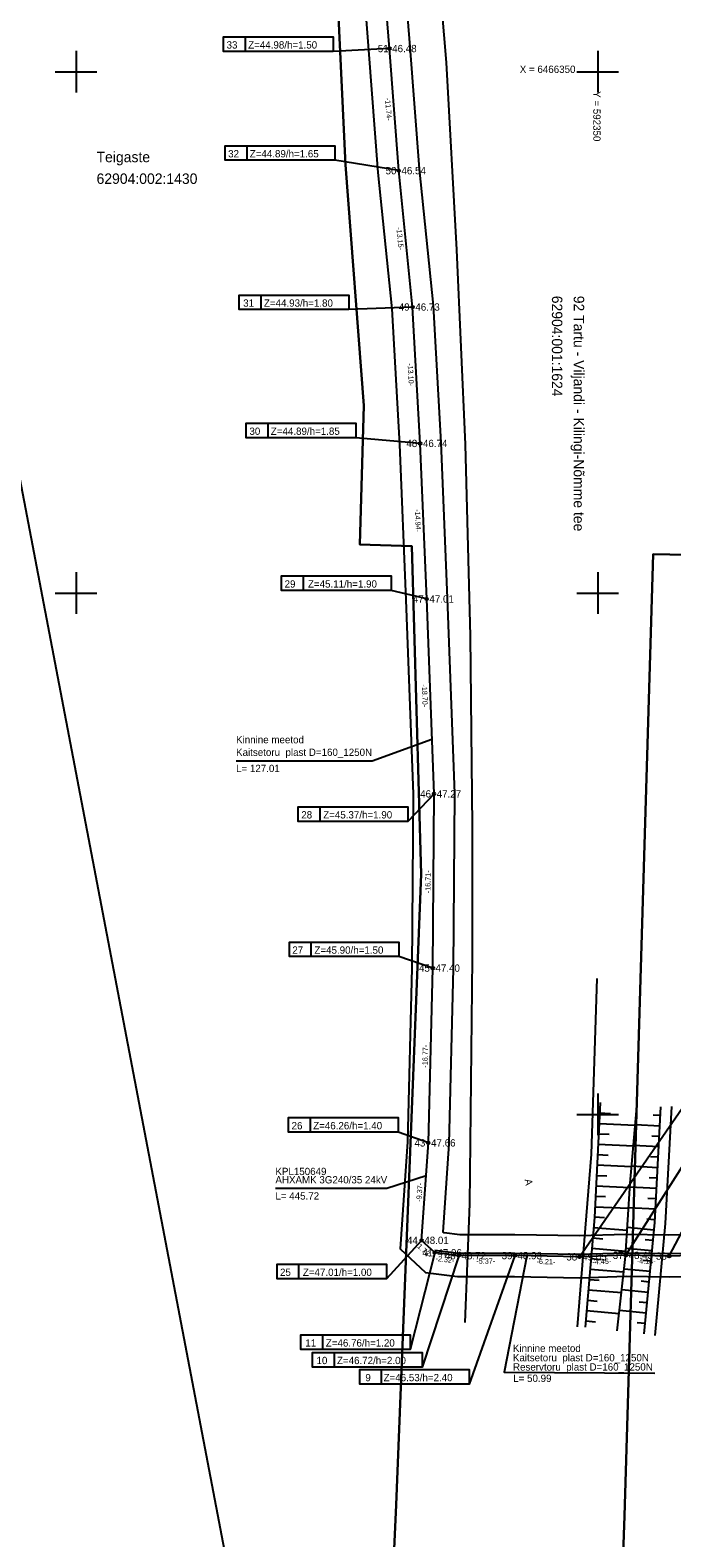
# Model space of a CAD drawing. Extents: x 592082 to 595437, y 6463338 to 6467739.
# Drawn here: x 592295.6 to 592357.1, y 6466209.4 to 6466354 of the extents above; entities that cross this region are included whole.
import ezdxf

# ---------------------------------------------------------------- set-up
doc = ezdxf.new("R2010")
doc.units = 0
for name, color, linetype in [('ABIJOONIS', 7, 'Continuous'), ('JOONSIDE', 7, 'Continuous'), ('KOORDPUNKT', 7, 'Continuous'), ('KPKAABEL', 7, 'Continuous'), ('MOOTKORG-EH2000', 7, 'Continuous'), ('MOOTMPUNKT', 7, 'Continuous'), ('MOOTNR', 7, 'Continuous'), ('MOOTPIIR', 7, 'Continuous'), ('PIIR', 7, 'Continuous'), ('RELJEEF', 7, 'Continuous'), ('TEE', 7, 'Continuous'), ('VORK', 7, 'Continuous'), ('VORMISTUS', 7, 'Continuous')]:
    doc.layers.add(name, color=color, linetype=linetype)

msp = doc.modelspace()

# ---------------------------------------------------------------- linework, layer by layer
at = {"layer": 'ABIJOONIS'}
for points in [[(592330.04, 6466352.22), (592324.63, 6466351.94), (592314.13, 6466351.94), (592314.13, 6466353.34), (592324.63, 6466353.34), (592324.63, 6466351.94)], [(592316.23, 6466351.94), (592316.23, 6466353.34)], [(592330.93, 6466340.51), (592324.8, 6466341.5), (592314.3, 6466341.5), (592314.3, 6466342.9), (592324.8, 6466342.9), (592324.8, 6466341.5)], [(592316.4, 6466341.5), (592316.4, 6466342.9)], [(592332.26, 6466327.43), (592326.15, 6466327.18), (592315.65, 6466327.18), (592315.65, 6466328.58), (592326.15, 6466328.58), (592326.15, 6466327.18)], [(592317.75, 6466327.18), (592317.75, 6466328.58)], [(592332.99, 6466314.35), (592326.82, 6466314.89), (592316.32, 6466314.89), (592316.32, 6466316.29), (592326.82, 6466316.29), (592326.82, 6466314.89)], [(592318.42, 6466314.89), (592318.42, 6466316.29)], [(592333.61, 6466299.43), (592330.19, 6466300.24), (592319.69, 6466300.24), (592319.69, 6466301.64), (592330.19, 6466301.64), (592330.19, 6466300.24)], [(592321.79, 6466300.24), (592321.79, 6466301.64)], [(592334.31, 6466280.74), (592331.79, 6466278.1), (592321.29, 6466278.1), (592321.29, 6466279.5), (592331.79, 6466279.5), (592331.79, 6466278.1)], [(592323.39, 6466278.1), (592323.39, 6466279.5)], [(592334.19, 6466264.03), (592330.95, 6466265.13), (592320.45, 6466265.13), (592320.45, 6466266.53), (592330.95, 6466266.53), (592330.95, 6466265.13)], [(592322.55, 6466265.13), (592322.55, 6466266.53)], [(592348.25, 6466236.34), (592362.1, 6466256.38), (592372.6, 6466256.38), (592372.6, 6466257.78), (592362.1, 6466257.78), (592362.1, 6466256.38)], [(592352.7, 6466236.49), (592364.21, 6466254.61), (592374.71, 6466254.61), (592374.71, 6466256.01), (592364.21, 6466256.01), (592364.21, 6466254.61)], [(592356.84, 6466236.41), (592365.39, 6466252.59), (592375.89, 6466252.59), (592375.89, 6466253.99), (592365.39, 6466253.99), (592365.39, 6466252.59)], [(592333.77, 6466247.27), (592330.87, 6466248.29), (592320.37, 6466248.29), (592320.37, 6466249.69), (592330.87, 6466249.69), (592330.87, 6466248.29)], [(592322.47, 6466248.29), (592322.47, 6466249.69)], [(592333.12, 6466237.92), (592329.77, 6466234.23), (592319.27, 6466234.23), (592319.27, 6466235.63), (592329.77, 6466235.63), (592329.77, 6466234.23)], [(592334.38, 6466236.74), (592332.04, 6466227.45), (592321.54, 6466227.45), (592321.54, 6466228.85), (592332.04, 6466228.85), (592332.04, 6466227.45)], [(592321.37, 6466234.23), (592321.37, 6466235.63)], [(592336.68, 6466236.45), (592333.18, 6466225.77), (592322.68, 6466225.77), (592322.68, 6466227.17), (592333.18, 6466227.17), (592333.18, 6466225.77)], [(592342.05, 6466236.46), (592337.69, 6466224.13), (592327.19, 6466224.13), (592327.19, 6466225.53), (592337.69, 6466225.53), (592337.69, 6466224.13)], [(592323.64, 6466227.45), (592323.64, 6466228.85)], [(592324.78, 6466225.77), (592324.78, 6466227.17)], [(592329.29, 6466224.13), (592329.29, 6466225.53)]]:
    msp.add_lwpolyline(points, dxfattribs=at)
at = {"layer": 'KOORDPUNKT'}
for centre, radius in [((592330.04, 6466352.22), 0.125), ((592330.04, 6466352.22), 0.011), ((592330.04, 6466352.22), 0.0125), ((592330.04, 6466352.22), 0.00511), ((592330.04, 6466352.22), 0.00659), ((592330.04, 6466352.22), 0.00807), ((592330.04, 6466352.22), 0.00955), ((592330.04, 6466352.22), 0.00215), ((592330.04, 6466352.22), 0.00363), ((592330.93, 6466340.51), 0.125), ((592330.93, 6466340.51), 0.00511), ((592330.93, 6466340.51), 0.00659), ((592330.93, 6466340.51), 0.00807), ((592330.93, 6466340.51), 0.00955), ((592330.93, 6466340.51), 0.011), ((592330.93, 6466340.51), 0.0125), ((592330.93, 6466340.51), 0.00215), ((592330.93, 6466340.51), 0.00363), ((592332.26, 6466327.43), 0.125), ((592332.26, 6466327.43), 0.011), ((592332.26, 6466327.43), 0.0125), ((592332.26, 6466327.43), 0.00511), ((592332.26, 6466327.43), 0.00659), ((592332.26, 6466327.43), 0.00807), ((592332.26, 6466327.43), 0.00955), ((592332.26, 6466327.43), 0.00215), ((592332.26, 6466327.43), 0.00363), ((592332.99, 6466314.35), 0.125), ((592332.99, 6466314.35), 0.011), ((592332.99, 6466314.35), 0.0125), ((592332.99, 6466314.35), 0.00659), ((592332.99, 6466314.35), 0.00807), ((592332.99, 6466314.35), 0.00955), ((592332.99, 6466314.35), 0.00215), ((592332.99, 6466314.35), 0.00363), ((592332.99, 6466314.35), 0.00511), ((592333.61, 6466299.43), 0.125), ((592333.61, 6466299.43), 0.00807), ((592333.61, 6466299.43), 0.00955), ((592333.61, 6466299.43), 0.011), ((592333.61, 6466299.43), 0.0125), ((592333.61, 6466299.43), 0.00511), ((592333.61, 6466299.43), 0.00659), ((592333.61, 6466299.43), 0.00215), ((592333.61, 6466299.43), 0.00363), ((592334.31, 6466280.74), 0.125), ((592334.31, 6466280.74), 0.011), ((592334.31, 6466280.74), 0.0125), ((592334.31, 6466280.74), 0.00511), ((592334.31, 6466280.74), 0.00659), ((592334.31, 6466280.74), 0.00807), ((592334.31, 6466280.74), 0.00955), ((592334.31, 6466280.74), 0.00215), ((592334.31, 6466280.74), 0.00363), ((592334.19, 6466264.03), 0.125), ((592334.19, 6466264.03), 0.011), ((592334.19, 6466264.03), 0.0125), ((592334.19, 6466264.03), 0.00807), ((592334.19, 6466264.03), 0.00955), ((592334.19, 6466264.03), 0.00215), ((592334.19, 6466264.03), 0.00363), ((592334.19, 6466264.03), 0.00511), ((592334.19, 6466264.03), 0.00659), ((592333.77, 6466247.27), 0.125), ((592333.77, 6466247.27), 0.011), ((592333.77, 6466247.27), 0.0125), ((592333.77, 6466247.27), 0.00511), ((592333.77, 6466247.27), 0.00659), ((592333.77, 6466247.27), 0.00807), ((592333.77, 6466247.27), 0.00955), ((592333.77, 6466247.27), 0.00215), ((592333.77, 6466247.27), 0.00363), ((592333.12, 6466237.92), 0.125), ((592333.12, 6466237.92), 0.00955), ((592333.12, 6466237.92), 0.011), ((592333.12, 6466237.92), 0.0125), ((592333.12, 6466237.92), 0.00511), ((592333.12, 6466237.92), 0.00659), ((592333.12, 6466237.92), 0.00807), ((592333.12, 6466237.92), 0.00215), ((592333.12, 6466237.92), 0.00363), ((592334.38, 6466236.74), 0.125), ((592334.38, 6466236.74), 0.011), ((592334.38, 6466236.74), 0.0125), ((592334.38, 6466236.74), 0.00363), ((592334.38, 6466236.74), 0.00511), ((592334.38, 6466236.74), 0.00659), ((592334.38, 6466236.74), 0.00807), ((592334.38, 6466236.74), 0.00955), ((592334.38, 6466236.74), 0.00215), ((592336.68, 6466236.45), 0.125), ((592336.68, 6466236.45), 0.011), ((592336.68, 6466236.45), 0.0125), ((592336.68, 6466236.45), 0.00807), ((592336.68, 6466236.45), 0.00955), ((592336.68, 6466236.45), 0.00215), ((592336.68, 6466236.45), 0.00363), ((592336.68, 6466236.45), 0.00511), ((592336.68, 6466236.45), 0.00659), ((592342.05, 6466236.46), 0.125), ((592342.05, 6466236.46), 0.0125), ((592342.05, 6466236.46), 0.00215), ((592342.05, 6466236.46), 0.00363), ((592342.05, 6466236.46), 0.00511), ((592342.05, 6466236.46), 0.00659), ((592342.05, 6466236.46), 0.00807), ((592342.05, 6466236.46), 0.00955), ((592342.05, 6466236.46), 0.011), ((592348.25, 6466236.34), 0.125), ((592348.25, 6466236.34), 0.00807), ((592348.25, 6466236.34), 0.00955), ((592348.25, 6466236.34), 0.011), ((592348.25, 6466236.34), 0.0125), ((592348.25, 6466236.34), 0.00511), ((592348.25, 6466236.34), 0.00659), ((592348.25, 6466236.34), 0.00215), ((592348.25, 6466236.34), 0.00363), ((592352.7, 6466236.49), 0.125), ((592352.7, 6466236.49), 0.0125), ((592352.7, 6466236.49), 0.00511), ((592352.7, 6466236.49), 0.00659), ((592352.7, 6466236.49), 0.00807), ((592352.7, 6466236.49), 0.00955), ((592352.7, 6466236.49), 0.011), ((592352.7, 6466236.49), 0.00215), ((592352.7, 6466236.49), 0.00363), ((592356.84, 6466236.41), 0.125), ((592356.84, 6466236.41), 0.00511), ((592356.84, 6466236.41), 0.00659), ((592356.84, 6466236.41), 0.00807), ((592356.84, 6466236.41), 0.00955), ((592356.84, 6466236.41), 0.011), ((592356.84, 6466236.41), 0.0125), ((592356.84, 6466236.41), 0.00363), ((592356.84, 6466236.41), 0.00215)]:
    msp.add_circle(centre, radius, dxfattribs=at)
at = {"layer": 'KPKAABEL'}
for points in [[(592334.38, 6466236.74), (592333.12, 6466237.92), (592333.77, 6466247.27), (592334.19, 6466264.03), (592334.31, 6466280.74), (592333.61, 6466299.43), (592332.99, 6466314.35), (592332.26, 6466327.43), (592330.93, 6466340.51), (592330.04, 6466352.22), (592329.53, 6466358.57), (592328.87, 6466362.95)], [(592361.9, 6466236.56), (592356.84, 6466236.41), (592352.7, 6466236.49), (592348.25, 6466236.34), (592342.05, 6466236.46), (592336.68, 6466236.45), (592334.38, 6466236.74), (592333.12, 6466237.92), (592333.77, 6466247.27), (592334.19, 6466264.03), (592334.31, 6466280.74), (592333.61, 6466299.43), (592332.99, 6466314.35), (592332.26, 6466327.43), (592330.93, 6466340.51), (592330.04, 6466352.22), (592329.53, 6466358.57)], [(592334.11, 6466285.94), (592328.39, 6466283.88), (592315.34, 6466283.88)], [(592333.55, 6466244.11), (592329.78, 6466242.88), (592319.11, 6466242.88)], [(592385.3, 6466235.94), (592380.55, 6466236.55), (592368.99, 6466236.66), (592361.9, 6466236.56), (592356.84, 6466236.41), (592352.7, 6466236.49), (592348.25, 6466236.34), (592342.05, 6466236.46), (592336.68, 6466236.45), (592334.38, 6466236.74)], [(592385.29, 6466236.15), (592380.57, 6466236.76), (592368.99, 6466236.87), (592361.9, 6466236.77), (592356.84, 6466236.62), (592352.7, 6466236.7), (592348.25, 6466236.55), (592342.05, 6466236.67), (592336.69, 6466236.66), (592334.4, 6466236.94)], [(592343.19, 6466236.44), (592341.04, 6466225.28), (592355.47, 6466225.18)]]:
    msp.add_lwpolyline(points, dxfattribs=at)
at = {"layer": 'MOOTMPUNKT'}
for centre in [(592330.04, 6466352.22), (592330.93, 6466340.51), (592332.26, 6466327.43), (592332.99, 6466314.35), (592333.61, 6466299.43), (592334.31, 6466280.74), (592334.19, 6466264.03), (592333.77, 6466247.27), (592333.12, 6466237.92), (592334.38, 6466236.74), (592336.68, 6466236.45), (592342.05, 6466236.46), (592348.25, 6466236.34), (592352.7, 6466236.49), (592356.84, 6466236.41)]:
    msp.add_circle(centre, 0.1, dxfattribs=at)
at = {"layer": 'MOOTPIIR'}
for points in [[(592327.54, 6466358.34), (592328.04, 6466352.06), (592328.94, 6466340.33), (592330.26, 6466327.27), (592330.99, 6466314.26), (592331.61, 6466299.35), (592332.31, 6466280.71), (592332.2, 6466264.06), (592331.77, 6466247.36), (592331.06, 6466237.11), (592333.49, 6466234.83), (592336.56, 6466234.45), (592342.03, 6466234.46), (592348.27, 6466234.34), (592352.71, 6466234.49), (592356.85, 6466234.41), (592361.95, 6466234.56), (592369, 6466234.66), (592380.41, 6466234.56)], [(592361.86, 6466238.56), (592356.83, 6466238.41), (592352.68, 6466238.49), (592348.24, 6466238.34), (592342.07, 6466238.46), (592336.8, 6466238.45), (592335.27, 6466238.64), (592335.18, 6466238.72), (592335.77, 6466247.17), (592336.19, 6466263.99), (592336.31, 6466280.77), (592335.61, 6466299.51), (592334.99, 6466314.45), (592334.25, 6466327.59), (592332.92, 6466340.69), (592332.03, 6466352.38), (592331.52, 6466358.79)]]:
    msp.add_lwpolyline(points, dxfattribs=at)
at = {"layer": 'PIIR'}
for points in [[(592338.84, 6466527.4), (592343.9, 6466494.98), (592357.09, 6466377.87), (592360.63, 6466318.19), (592360.11, 6466303.63), (592355.31, 6466303.74), (592352.58, 6466211.49), (592350.73, 6466159.48)], [(592328.39, 6466161.56), (592330.68, 6466212.56), (592333.09, 6466273.04), (592332.2, 6466304.49), (592327.21, 6466304.64), (592327.6, 6466317.98), (592325.82, 6466341.08), (592324.22, 6466374.94), (592321.58, 6466398.13), (592311.21, 6466490.43), (592308.62, 6466505.7)]]:
    msp.add_lwpolyline(points, dxfattribs=at)
for points in [[(592273.24, 6466434.31), (592321.58, 6466398.13), (592324.22, 6466374.94), (592325.82, 6466341.08), (592327.6, 6466317.98), (592327.21, 6466304.64), (592332.2, 6466304.49), (592333.09, 6466273.04), (592330.68, 6466212.56), (592328.39, 6466161.56), (592325.41, 6466117.99), (592202.04, 6466290.93)], [(592357.09, 6466377.87), (592364.1, 6466392.22), (592368.77, 6466376.93), (592372.7, 6466240.06), (592365.98, 6466124.11), (592354.23, 6466082.68), (592346.03, 6466093.17), (592345.81, 6466093.45), (592350.73, 6466159.48), (592352.58, 6466211.49), (592355.31, 6466303.74), (592360.11, 6466303.63), (592360.63, 6466318.19)]]:
    msp.add_lwpolyline(points, close=True, dxfattribs=at)
at = {"layer": 'RELJEEF'}
for p, q in [((592350.18, 6466250.14), (592351.23, 6466250.09)), ((592356.01, 6466249.88), (592355.32, 6466249.92)), ((592350.13, 6466249.14), (592353.6, 6466248.98)), ((592355.96, 6466248.88), (592353.61, 6466249.01)), ((592350.03, 6466247.15), (592353.42, 6466246.98)), ((592350.08, 6466248.15), (592351.11, 6466248.1)), ((592355.85, 6466246.89), (592353.43, 6466247.02)), ((592355.9, 6466247.89), (592355.19, 6466247.92)), ((592349.98, 6466246.15), (592350.99, 6466246.1)), ((592355.8, 6466245.89), (592355.06, 6466245.93)), ((592349.89, 6466244.15), (592350.87, 6466244.1)), ((592349.93, 6466245.15), (592353.25, 6466244.99)), ((592355.74, 6466244.89), (592353.25, 6466245.03)), ((592349.84, 6466243.15), (592353.08, 6466242.99)), ((592355.63, 6466242.89), (592353.08, 6466243.03)), ((592355.69, 6466243.89), (592354.93, 6466243.93)), ((592349.74, 6466241.15), (592352.96, 6466241)), ((592349.79, 6466242.15), (592350.76, 6466242.11)), ((592355.58, 6466241.89), (592354.81, 6466241.94)), ((592349.69, 6466240.16), (592350.65, 6466240.11)), ((592355.53, 6466240.9), (592352.96, 6466241.04)), ((592355.47, 6466239.9), (592354.7, 6466239.94)), ((592349.61, 6466239.16), (592352.83, 6466238.89)), ((592355.39, 6466238.9), (592352.84, 6466239.14)), ((592349.44, 6466237.17), (592352.7, 6466236.89)), ((592349.52, 6466238.16), (592350.5, 6466238.08)), ((592355.2, 6466236.91), (592352.72, 6466237.15)), ((592355.29, 6466237.91), (592354.54, 6466237.98)), ((592349.35, 6466236.17), (592350.33, 6466236.09)), ((592355.11, 6466235.91), (592354.37, 6466235.98)), ((592349.19, 6466234.18), (592350.15, 6466234.09)), ((592349.27, 6466235.17), (592352.51, 6466234.9)), ((592355.01, 6466234.92), (592352.54, 6466235.15)), ((592354.92, 6466233.92), (592354.17, 6466233.99)), ((592349.1, 6466233.18), (592352.28, 6466232.91)), ((592354.82, 6466232.93), (592352.31, 6466233.17)), ((592348.93, 6466231.19), (592352.06, 6466230.92)), ((592349.02, 6466232.18), (592349.96, 6466232.1)), ((592354.63, 6466230.94), (592352.09, 6466231.18)), ((592354.73, 6466231.93), (592353.97, 6466232)), ((592348.85, 6466230.19), (592349.78, 6466230.11)), ((592354.54, 6466229.94), (592353.77, 6466230.01))]:
    msp.add_line(p, q, dxfattribs=at)
for points in [[(592350.23, 6466251.14), (592349.69, 6466240.1), (592348.8, 6466229.6)], [(592351.87, 6466229.24), (592352.67, 6466236.36), (592353.1, 6466243.42), (592353.72, 6466250.34)], [(592354.45, 6466228.95), (592355.46, 6466239.62), (592356.06, 6466250.74)]]:
    msp.add_lwpolyline(points, dxfattribs=at)
at = {"layer": 'TEE'}
for points in [[(592337.3, 6466230.04), (592337.75, 6466241.41), (592337.99, 6466264.94), (592338.01, 6466277.63), (592337.8, 6466295.86), (592337.32, 6466314.25), (592336.49, 6466332.9), (592335.51, 6466350.88), (592333.88, 6466370.25), (592332.12, 6466389.07), (592330.38, 6466408.49), (592328.37, 6466427.77), (592326.25, 6466446.28), (592323.72, 6466464.45), (592320.93, 6466483.78), (592318.23, 6466502.74), (592315.51, 6466521.44), (592312.26, 6466541.37), (592308.71, 6466560.32), (592304.84, 6466579.03), (592300, 6466600.78)], [(592349.9, 6466263.04), (592349.38, 6466246.19), (592348.04, 6466229.64)], [(592357.08, 6466250.75), (592356.47, 6466239.53), (592355.47, 6466228.8)]]:
    msp.add_lwpolyline(points, dxfattribs=at)
at = {"layer": 'VORK'}
for p, q in [((592300, 6466352), (592300, 6466348)), ((592350, 6466352), (592350, 6466348)), ((592298, 6466350), (592302, 6466350)), ((592348, 6466350), (592352, 6466350)), ((592300, 6466302), (592300, 6466298)), ((592350, 6466302), (592350, 6466298)), ((592298, 6466300), (592302, 6466300)), ((592348, 6466300), (592352, 6466300)), ((592350, 6466252), (592350, 6466248)), ((592348, 6466250), (592352, 6466250))]:
    msp.add_line(p, q, dxfattribs=at)
at = {"layer": 'VORMISTUS'}
msp.add_lwpolyline([(592337.47, 6466086.39), (592478.43, 6466113.3), (592369.31, 6466684.98), (592228.36, 6466658.08)], close=True, dxfattribs=at)

# ---------------------------------------------------------------- texts
at = {"layer": 'ABIJOONIS'}
for s, p in [('33', (592314.43, 6466352.22)), ('Z=44.98/h=1.50', (592316.5, 6466352.22)), ('32', (592314.58, 6466341.78)), ('Z=44.89/h=1.65', (592316.65, 6466341.78)), ('31', (592316.02, 6466327.46)), ('Z=44.93/h=1.80', (592318.01, 6466327.46)), ('30', (592316.62, 6466315.17)), ('Z=44.89/h=1.85', (592318.67, 6466315.17)), ('29', (592319.99, 6466300.52)), ('Z=45.11/h=1.90', (592322.23, 6466300.52)), ('28', (592321.59, 6466278.38)), ('Z=45.37/h=1.90', (592323.69, 6466278.38)), ('27', (592320.73, 6466265.41)), ('Z=45.90/h=1.50', (592322.85, 6466265.41)), ('26', (592320.66, 6466248.57)), ('Z=46.26/h=1.40', (592322.73, 6466248.57)), ('25', (592319.55, 6466234.51)), ('Z=47.01/h=1.00', (592321.74, 6466234.51)), ('11', (592321.98, 6466227.73)), ('Z=46.76/h=1.20', (592323.94, 6466227.73)), ('10', (592323.05, 6466226.05)), ('Z=46.72/h=2.00', (592325.01, 6466226.05)), ('9', (592327.73, 6466224.41)), ('Z=46.53/h=2.40', (592329.48, 6466224.41))]:
    msp.add_text(s, height=0.7, dxfattribs=at).set_placement(p)
at = {"layer": 'JOONSIDE'}
for s, rotation, p in [('-11.74-', 274.3706, (592329.62, 6466347.48)), ('-13.15-', 275.7891, (592330.7, 6466335.06)), ('-13.10-', 273.217, (592331.78, 6466322.02)), ('-14.94-', 272.3829, (592332.48, 6466308.03)), ('-18.70-', 272.1264, (592333.14, 6466291.23)), ('-16.71-', 89.6195, (592333.97, 6466271.21)), ('-16.77-', 88.5442, (592333.68, 6466254.48)), ('-9.37-', 86.0289, (592333.1, 6466241.61)), ('-1.73-', 316.8082, (592332.49, 6466237.44)), ('-2.32-', 353.0464, (592334.44, 6466235.95)), ('-5.37-', 0.0961, (592338.37, 6466235.68)), ('-6.21-', 358.8646, (592344.13, 6466235.65)), ('-4.45-', 1.9709, (592349.5, 6466235.61)), ('-4.14-', 358.8794, (592353.75, 6466235.7))]:
    msp.add_text(s, height=0.5, rotation=rotation, dxfattribs=at).set_placement(p)
at = {"layer": 'KPKAABEL'}
for s, p in [('Kinnine meetod', (592315.34, 6466285.59)), ('Kaitsetoru  plast D=160_1250N', (592315.34, 6466284.38)), ('L= 127.01', (592315.34, 6466282.83)), ('AHXAMK 3G240/35 24kV', (592319.11, 6466243.38)), ('KPL150649', (592319.11, 6466244.18)), ('L= 445.72', (592319.11, 6466241.83)), ('Kinnine meetod', (592341.87, 6466227.22)), ('Kaitsetoru  plast D=160_1250N', (592341.87, 6466226.32)), ('Reservtoru  plast D=160_1250N', (592341.88, 6466225.43)), ('L= 50.99', (592341.9, 6466224.34))]:
    msp.add_text(s, height=0.7, dxfattribs=at).set_placement(p)
at = {"layer": 'MOOTKORG-EH2000'}
for s, p in [(' 46.48', (592330.04, 6466351.87)), (' 46.54', (592330.93, 6466340.16)), (' 46.73', (592332.26, 6466327.08)), (' 46.74', (592332.99, 6466314)), (' 47.01', (592333.61, 6466299.08)), (' 47.27', (592334.31, 6466280.39)), (' 47.40', (592334.19, 6466263.68)), (' 47.66', (592333.77, 6466246.92)), (' 48.01', (592333.12, 6466237.57)), (' 47.96', (592334.38, 6466236.38)), (' 48.72', (592336.68, 6466236.1)), (' 48.93', (592342.05, 6466236.11)), (' 48.43', (592352.7, 6466236.14)), (' 49.05', (592348.25, 6466235.99))]:
    msp.add_text(s, height=0.7, dxfattribs=at).set_placement(p)
at = {"layer": 'MOOTNR'}
for s, p in [('51 ', (592328.92, 6466351.87)), ('50 ', (592329.67, 6466340.16)), ('49 ', (592330.93, 6466327.08)), ('48 ', (592331.66, 6466314)), ('47 ', (592332.28, 6466299.08)), ('46 ', (592332.98, 6466280.39)), ('45 ', (592332.87, 6466263.68)), ('43 ', (592332.44, 6466246.92)), ('44 ', (592331.72, 6466237.57)), ('41 ', (592333.19, 6466236.38)), ('40 ', (592335.35, 6466236.1)), ('39 ', (592340.79, 6466236.11)), ('37 ', (592351.44, 6466236.14)), ('36 ', (592355.58, 6466236.06)), ('38 ', (592346.99, 6466235.99))]:
    msp.add_text(s, height=0.7, dxfattribs=at).set_placement(p)
at = {"layer": 'PIIR'}
for s, p in [('Teigaste', (592301.97, 6466341.32)), ('62904:002:1430', (592301.97, 6466339.24))]:
    msp.add_text(s, height=1, dxfattribs=at).set_placement(p)
for s, p in [('62904:001:1624', (592345.61, 6466328.51)), ('92 Tartu - Viljandi - Kilingi-Nõmme tee', (592347.7, 6466328.51))]:
    msp.add_text(s, height=1, rotation=270, dxfattribs=at).set_placement(p)
at = {"layer": 'TEE'}
msp.add_text('A', height=0.7, rotation=279.9579, dxfattribs=at).set_placement((592342.99, 6466243.75))
at = {"layer": 'VORK'}
msp.add_text('X = 6466350', height=0.7, dxfattribs=at).set_placement((592342.53, 6466349.88))
msp.add_text('Y = 592350 ', height=0.7, rotation=270, dxfattribs=at).set_placement((592349.57, 6466348.13))

doc.saveas('drawing.dxf')
